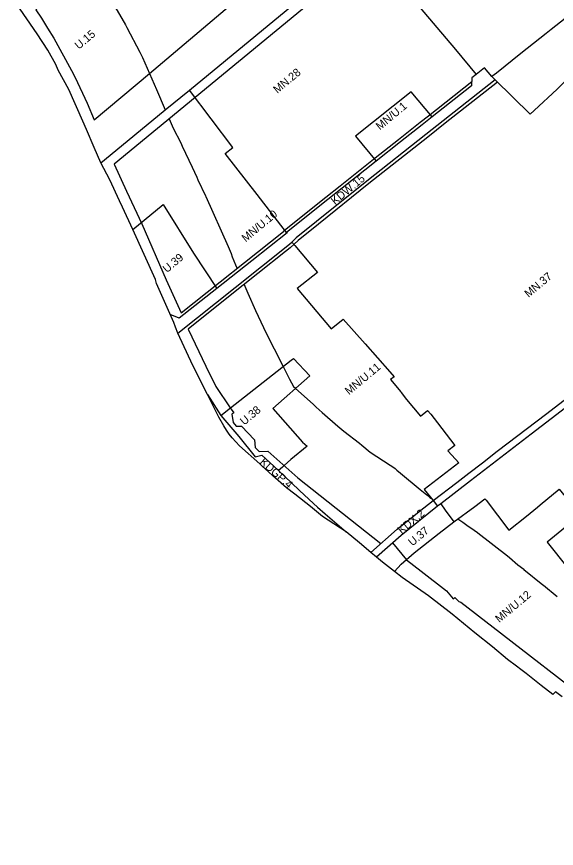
# Model space of a CAD drawing. Extents: x 7418616 to 7420822, y 5550745 to 5553106.
# Drawn here: x 7418940 to 7419277, y 5551665 to 5552185 of the extents above; entities that cross this region are included whole.
import ezdxf

# ---------------------------------------------------------------- set-up
doc = ezdxf.new("R2010")
doc.units = 0
for name, color, linetype in [('granica obszaru objętego planem', 7, 'Continuous'), ('granica strefy zwiększonej wysokości zabudowy', 7, 'Continuous'), ('linie rozgraniczające', 7, 'Continuous'), ('nieprzekraczalne linie zabudowy', 7, 'Continuous'), ('przeznaczenia terenów', 7, 'Continuous')]:
    doc.layers.add(name, color=color, linetype=linetype)

msp = doc.modelspace()

# ---------------------------------------------------------------- linework, layer by layer
at = {"layer": 'granica obszaru objętego planem'}
msp.add_lwpolyline([(7419280.87, 5551760.17), (7419276.65, 5551763.24), (7419274.84, 5551761.48), (7419267.57, 5551767.25), (7419258.19, 5551774.68), (7419255.06, 5551777.16), (7419252.21, 5551779.28), (7419246.71, 5551783.36), (7419237.17, 5551791.27), (7419226.14, 5551800.04), (7419215.72, 5551808.8), (7419212, 5551811.84), (7419197.38, 5551823.15), (7419180.78, 5551834.64), (7419176.02, 5551838.41), (7419168.54, 5551844.15), (7419164.73, 5551847.37), (7419161.39, 5551850.32), (7419154.23, 5551856.38), (7419145.8, 5551863.09), (7419131.04, 5551872.72), (7419123.57, 5551878.98), (7419113.77, 5551886.59), (7419108.61, 5551890.61), (7419100.18, 5551898.11), (7419097.34, 5551900.54), (7419093.39, 5551904.24), (7419091.89, 5551905.6), (7419079.33, 5551916.89), (7419074.65, 5551921.78), (7419072.83, 5551924.05), (7419071.13, 5551926.55), (7419069.46, 5551929.3), (7419066.38, 5551934.83), (7419059.23, 5551948.92), (7419050.09, 5551966.95), (7419040.75, 5551987.32), (7419039.4, 5551990.98), (7419038.19, 5551993.83), (7419027.46, 5552018.26), (7419026.74, 5552020.83), (7419012.67, 5552051.97), (7419006.17, 5552065.96), (7419004.4, 5552069.77), (7418998.24, 5552083.02), (7418992.73, 5552093.59), (7418988.54, 5552103.22), (7418983.66, 5552114.46), (7418981.47, 5552119.52), (7418972.81, 5552139.43), (7418966.12, 5552151.37), (7418964.68, 5552154.91), (7418959.51, 5552163.91), (7418952.89, 5552174.15), (7418940.12, 5552192.95)], dxfattribs=at)
at = {"layer": 'granica strefy zwiększonej wysokości zabudowy'}
for points in [[(7419035.42, 5552120.99), (7419037.88, 5552115.15), (7419042.58, 5552106.13), (7419043.08, 5552105.13), (7419043.58, 5552104.1), (7419049.74, 5552090.85), (7419049.74, 5552090.84), (7419052.58, 5552084.74)], [(7419052.58, 5552084.74), (7419053.36, 5552083.06), (7419058.01, 5552073.04), (7419058.24, 5552072.56), (7419072.31, 5552041.42), (7419072.93, 5552039.96), (7419074.09, 5552036.9), (7419074.71, 5552034.95), (7419076.88, 5552029.88), (7419077.81, 5552027.71)], [(7419082.13, 5552017.61), (7419082.61, 5552016.49), (7419083.16, 5552015.21), (7419084.52, 5552012.14), (7419089.29, 5552001.43), (7419094.2, 5551990.72), (7419095.31, 5551988.51), (7419106.47, 5551966.38), (7419110.42, 5551958.54), (7419113.03, 5551953.99), (7419114.15, 5551952.82), (7419114.31, 5551952.68), (7419125.32, 5551942.79), (7419125.48, 5551942.64), (7419126.98, 5551941.28), (7419127.16, 5551941.11), (7419130.8, 5551937.78), (7419140.61, 5551929.06), (7419144.47, 5551926.06), (7419154.24, 5551918.47), (7419155.69, 5551917.3), (7419160.89, 5551912.94), (7419173.36, 5551904.77), (7419173.76, 5551904.51), (7419176.42, 5551902.61), (7419177.47, 5551901.77), (7419179.76, 5551899.88), (7419192.05, 5551889.68), (7419192.07, 5551889.66), (7419196.26, 5551886.18), (7419198.13, 5551884.7), (7419199.12, 5551883.98)], [(7419215.69, 5551871.28), (7419218.7, 5551869.2), (7419221.3, 5551867.4), (7419225.84, 5551864.26), (7419227.82, 5551862.82), (7419228.19, 5551862.53), (7419246.53, 5551848.18), (7419247.89, 5551847.08), (7419253.16, 5551842.65), (7419256.75, 5551839.75), (7419256.78, 5551839.73), (7419268.62, 5551830.14), (7419269.08, 5551829.76), (7419277.58, 5551822.71)]]:
    msp.add_lwpolyline(points, dxfattribs=at)
at = {"layer": 'linie rozgraniczające'}
for p, q in [((7419236.93, 5552147.47), (7419238.99, 5552145.43)), ((7419032.89, 5552126.63), (7419047.97, 5552139.03)), ((7419059.23, 5551948.92), (7419067.6, 5551935.79)), ((7419200.17, 5551882.67), (7419202.91, 5551879.1)), ((7419204.9, 5551880.69), (7419202.91, 5551879.1))]:
    msp.add_line(p, q, dxfattribs=at)
for points in [[(7418957.84, 5552251.35), (7418958.23, 5552250.88), (7418979.79, 5552223.39), (7418981.48, 5552221.04), (7418994.25, 5552202.25), (7419001.5, 5552191.05), (7419002.87, 5552188.82), (7419008.04, 5552179.82), (7419008.95, 5552178.16), (7419017.08, 5552162.68), (7419017.65, 5552161.54), (7419018.66, 5552159.37), (7419027.36, 5552139.38), (7419032.89, 5552126.63)], [(7419365.97, 5552250.04), (7419312.1, 5552206.93), (7419296.89, 5552194.85), (7419293.29, 5552192.01), (7419273.97, 5552176.76), (7419270.76, 5552174.26), (7419254.96, 5552161.91), (7419239.68, 5552149.67), (7419236.93, 5552147.47)], [(7419047.97, 5552139.03), (7419112.04, 5552191.72), (7419149.11, 5552222.2), (7419158.66, 5552230.06)], [(7419158.66, 5552230.06), (7419188.56, 5552194.58), (7419214.09, 5552164.29), (7419227.12, 5552148.84)], [(7419280.87, 5551760.17), (7419276.65, 5551763.24), (7419274.84, 5551761.48), (7419267.57, 5551767.25), (7419258.19, 5551774.68), (7419255.06, 5551777.16), (7419252.21, 5551779.28), (7419246.71, 5551783.36), (7419237.17, 5551791.27), (7419226.14, 5551800.04), (7419215.72, 5551808.8), (7419212, 5551811.84), (7419197.38, 5551823.15), (7419180.78, 5551834.64), (7419176.02, 5551838.41), (7419168.54, 5551844.15), (7419164.73, 5551847.37), (7419161.39, 5551850.32), (7419154.23, 5551856.38), (7419145.8, 5551863.09), (7419131.04, 5551872.72), (7419123.57, 5551878.98), (7419113.77, 5551886.59), (7419108.61, 5551890.61), (7419100.18, 5551898.11), (7419097.34, 5551900.54), (7419093.39, 5551904.24), (7419091.89, 5551905.6), (7419079.33, 5551916.89), (7419074.65, 5551921.78), (7419072.83, 5551924.05), (7419071.13, 5551926.55), (7419069.46, 5551929.3), (7419066.38, 5551934.83), (7419059.23, 5551948.92), (7419050.09, 5551966.95), (7419040.75, 5551987.32), (7419039.4, 5551990.98), (7419038.19, 5551993.83), (7419027.46, 5552018.26), (7419026.74, 5552020.83), (7419012.67, 5552051.97), (7419006.17, 5552065.96), (7419004.4, 5552069.77), (7418998.24, 5552083.02), (7418992.73, 5552093.59), (7418988.54, 5552103.22), (7418983.66, 5552114.46), (7418981.47, 5552119.52), (7418972.81, 5552139.43), (7418966.12, 5552151.37), (7418964.68, 5552154.91), (7418959.51, 5552163.91), (7418952.89, 5552174.15), (7418940.12, 5552192.95)], [(7419236.93, 5552147.47), (7419232.33, 5552152.92), (7419227.12, 5552148.84)], [(7419238.99, 5552145.43), (7419260.69, 5552123.96), (7419263.29, 5552126.31), (7419277.6, 5552139.69), (7419289.46, 5552151.49)], [(7419227.12, 5552148.84), (7419224.46, 5552146.75), (7419224.11, 5552141.78), (7419199.58, 5552122.28)], [(7419238.99, 5552145.43), (7419206.39, 5552119.9), (7419195.72, 5552111.26), (7419158.85, 5552082.15), (7419127.34, 5552056.89), (7419114.76, 5552046.72), (7419114.7, 5552046.67), (7419111.95, 5552044.15)], [(7419108.72, 5552050.09), (7419092.36, 5552071.09), (7419090.24, 5552073.81), (7419070.31, 5552099.36), (7419075.09, 5552103.2), (7419047.97, 5552139.03)], [(7419199.58, 5552122.28), (7419186.54, 5552137.92), (7419151.63, 5552110.16), (7419164.61, 5552094.58)], [(7418992.73, 5552093.59), (7418995, 5552095.47), (7419032.89, 5552126.63)], [(7419199.58, 5552122.28), (7419198.54, 5552121.45), (7419193.38, 5552117.43), (7419179.86, 5552106.62), (7419164.61, 5552094.58)], [(7419164.61, 5552094.58), (7419143.45, 5552077.74), (7419134.52, 5552070.61), (7419108.72, 5552050.09)], [(7419012.67, 5552051.97), (7419031.6, 5552067.49), (7419050.6, 5552037.11), (7419065.05, 5552015.07)], [(7419108.72, 5552050.09), (7419108.95, 5552049.8), (7419086.92, 5552032.37), (7419065.05, 5552015.07)], [(7419040.75, 5551987.32), (7419076.6, 5552015.77), (7419109.5, 5552041.89), (7419111.95, 5552044.15)], [(7419111.95, 5552044.15), (7419113.81, 5552041.94), (7419128.04, 5552025.15), (7419115.39, 5552015.18), (7419136.48, 5551990.01), (7419144.1, 5551996.01), (7419157.8, 5551980.49), (7419173.14, 5551963.05), (7419175.78, 5551960.05), (7419173.65, 5551958.32), (7419180.03, 5551950.49), (7419180.31, 5551950.13), (7419183.58, 5551945.83), (7419192.25, 5551935.4), (7419196.69, 5551938.89), (7419198.81, 5551936.74), (7419203.02, 5551931.24), (7419213.84, 5551917.15), (7419209.43, 5551913.77), (7419209.63, 5551913.56), (7419216.26, 5551906.35), (7419194.57, 5551889.62), (7419200.17, 5551882.67)], [(7419200.17, 5551882.67), (7419214.91, 5551893.91), (7419222.45, 5551899.78), (7419230.97, 5551906.24), (7419240.24, 5551913.47), (7419271.1, 5551937.05), (7419296.59, 5551956.64), (7419307.85, 5551965.65), (7419314.56, 5551971.02), (7419333.41, 5551985.96), (7419341.61, 5551992.46), (7419359.62, 5552006.02), (7419390.21, 5552029.04)], [(7419392.25, 5552024.94), (7419355.37, 5551996.55), (7419335.6, 5551981.33), (7419317.5, 5551967.39), (7419299.12, 5551953.24), (7419280.13, 5551938.61), (7419261.43, 5551924.21), (7419242.4, 5551909.56), (7419223.6, 5551895.08), (7419204.9, 5551880.69)], [(7419065.05, 5552015.07), (7419041.57, 5551996.5), (7419035.93, 5551998.97)], [(7419067.6, 5551935.79), (7419073.66, 5551940.54), (7419111.55, 5551970.38), (7419112.93, 5551971.47), (7419123.19, 5551960.53), (7419100.13, 5551940.16), (7419118.59, 5551919.23), (7419121.46, 5551916.69), (7419111.44, 5551908.25), (7419107.27, 5551904.63), (7419106.1, 5551903.56), (7419103.71, 5551901.36)], [(7419067.6, 5551935.79), (7419078.91, 5551922.6), (7419089.14, 5551910.08), (7419093.24, 5551910.96), (7419100.76, 5551904.07), (7419103.71, 5551901.36)], [(7419103.71, 5551901.36), (7419111.72, 5551893.86), (7419116.75, 5551889.07), (7419122.58, 5551883.51), (7419125.48, 5551880.75), (7419127.89, 5551878.65), (7419132.76, 5551874.39), (7419145.8, 5551863.09)], [(7419213.04, 5551869.32), (7419226.26, 5551879.01), (7419232.46, 5551883.78), (7419233.36, 5551882.9), (7419247.56, 5551864.17), (7419258.46, 5551872.91), (7419265.33, 5551878.57), (7419267.03, 5551879.97), (7419278.98, 5551889.81), (7419292.23, 5551873.48), (7419280.64, 5551864.29), (7419271.31, 5551856.81), (7419311.51, 5551806.43), (7419316.29, 5551801.08), (7419320.36, 5551796.74)], [(7419161.39, 5551850.32), (7419177.72, 5551864.74), (7419191.44, 5551875.95), (7419200.17, 5551882.67)], [(7419202.91, 5551879.1), (7419180.22, 5551860.96), (7419164.73, 5551847.37)], [(7419204.9, 5551880.69), (7419207.81, 5551876.77), (7419213.04, 5551869.32)], [(7419176.02, 5551838.41), (7419180.25, 5551842.93), (7419188.42, 5551850.11), (7419204.01, 5551862.39), (7419213.04, 5551869.32)]]:
    msp.add_lwpolyline(points, dxfattribs=at)
at = {"layer": 'nieprzekraczalne linie zabudowy'}
for points in [[(7418952.04, 5552189.16), (7418955.55, 5552183.91), (7418959.46, 5552177.78), (7418963.26, 5552171.4), (7418974.37, 5552151.34), (7418976.69, 5552146.79), (7418984.13, 5552130.89), (7418988.57, 5552120.49), (7419023, 5552149.4), (7419167.49, 5552271.78), (7419164.04, 5552276.25), (7419159.02, 5552282.23), (7419143.41, 5552297.76), (7419128.14, 5552312.81), (7419119.44, 5552320.59), (7419103.24, 5552334.55), (7419102.21, 5552335.54), (7418982.36, 5552218.45), (7418952.04, 5552189.16)], [(7419257.49, 5552304.03), (7419001.12, 5552092.71), (7419008.7, 5552075.95), (7419018.24, 5552055.41), (7419033.59, 5552020.49), (7419042.77, 5552000), (7419106.81, 5552050.65), (7419106.93, 5552050.97), (7419107.06, 5552051.2), (7419107.22, 5552051.41), (7419107.48, 5552051.65), (7419133.28, 5552072.17), (7419142.2, 5552079.3), (7419164.04, 5552096.68), (7419178.61, 5552108.18), (7419192.13, 5552118.99), (7419197.3, 5552123.02), (7419224.3, 5552144.42)], [(7419240.42, 5552144.02), (7419207.64, 5552118.34), (7419196.96, 5552109.69), (7419160.09, 5552080.59), (7419128.59, 5552055.33), (7419116.01, 5552045.15), (7419110.93, 5552040.5), (7419108.08, 5552038.21), (7419073.52, 5552010.77), (7419047.27, 5551989.71), (7419058.16, 5551966.61), (7419064.46, 5551953.91), (7419073.55, 5551940.56), (7419075.78, 5551937.57), (7419074.52, 5551936.62), (7419075.3, 5551931.46), (7419077.13, 5551929.21), (7419080.63, 5551929.09), (7419088.75, 5551920.55), (7419089.05, 5551915.75), (7419091.65, 5551913.32), (7419096.97, 5551913.54), (7419115.68, 5551896.83), (7419167.61, 5551855.81)], [(7419174.91, 5551856.3), (7419183.56, 5551845.76), (7419192.76, 5551838.5), (7419208.5, 5551826.3), (7419212.74, 5551821.26), (7419213.84, 5551822.17), (7419216.31, 5551819.63), (7419217.54, 5551819.28), (7419237.72, 5551803.64), (7419301.27, 5551754.54), (7419324.5, 5551737.35), (7419374.12, 5551691.34), (7419399.48, 5551667.41), (7419401.59, 5551665.49)]]:
    msp.add_lwpolyline(points, dxfattribs=at)

# ---------------------------------------------------------------- texts
at = {"layer": 'przeznaczenia terenów'}
for s, rotation, p in [('U.15', 39.8439, (7418978.94, 5552164.18)), ('MN.28', 39.8439, (7419102.93, 5552136.64)), ('MN/U.1', 39.8439, (7419166.96, 5552113.76)), ('KDW.15', 39.8439, (7419139, 5552067.06)), ('MN/U.10', 39.8439, (7419083.17, 5552043.87)), ('U.39', 39.8439, (7419033.93, 5552024.64)), ('MN.37', 39.8439, (7419259.77, 5552009.22)), ('MN/U.11', 39.8439, (7419147.67, 5551948.42)), ('U.38', 39.8439, (7419082.21, 5551929.44)), ('KDGP.4', 318.2512, (7419091.55, 5551906.16)), ('KDX.2', 39.8439, (7419180.54, 5551861.53)), ('U.37', 39.8439, (7419187.21, 5551853.98)), ('MN/U.12', 39.8439, (7419241.51, 5551806.16))]:
    msp.add_text(s, height=5, rotation=rotation, dxfattribs=at).set_placement(p)

doc.saveas('drawing.dxf')
